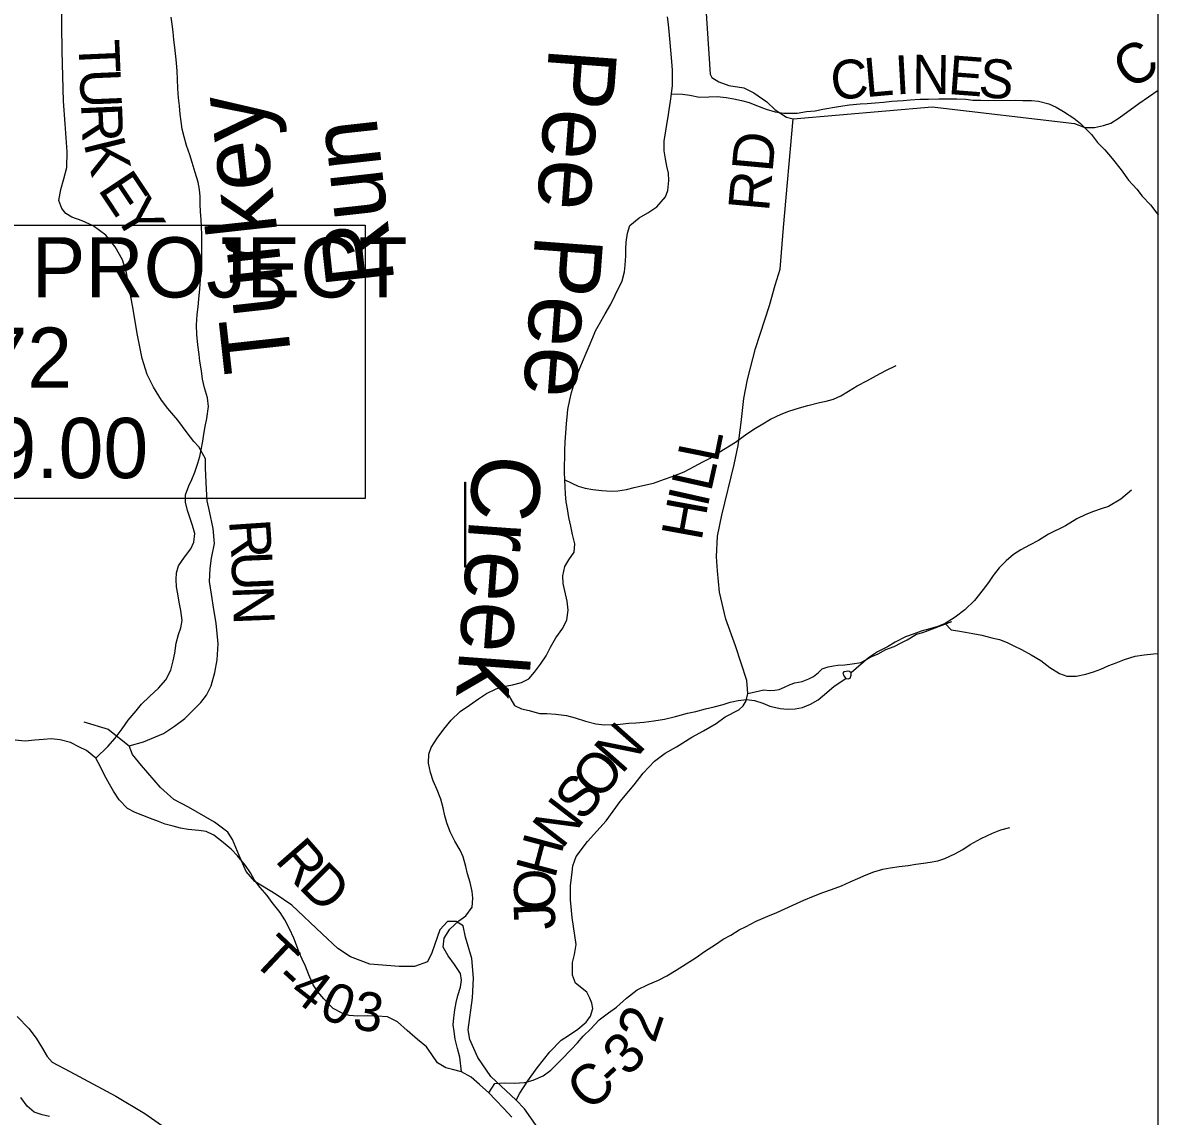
# Model space of a CAD drawing. Extents: x -139 to 835, y 0 to 440.
# Drawn here: x 242.7 to 295.5, y 238 to 288.9 of the extents above; entities that cross this region are included whole.
import ezdxf

# ---------------------------------------------------------------- set-up
doc = ezdxf.new("R2010")
doc.units = 0
for name, color, linetype in [('GM_X_County_Road', 7, 'Continuous'), ('GM_X_County_Road_Text', 7, 'Continuous'), ('GM_X_County_Text', 7, 'Continuous'), ('GM_X_Major_River', 7, 'Continuous'), ('GM_X_Minor_Lake', 7, 'Continuous'), ('GM_X_Minor_River', 7, 'Continuous'), ('GM_X_Minor_River_Text', 7, 'Continuous'), ('GM_X_Township_Road', 7, 'Continuous'), ('GM_X_Township_Road_Text', 7, 'Continuous'), ('SH_Cut_Line', 7, 'Continuous'), ('SH_Text', 7, 'Continuous')]:
    doc.layers.add(name, color=color, linetype=linetype)

msp = doc.modelspace()

# ---------------------------------------------------------------- linework, layer by layer
at = {"layer": 'GM_X_County_Road'}
for points in [[(274.092, 294.765), (274.624, 286.489), (274.713, 286.332), (275.03, 286.138), (275.5, 285.968), (276.199, 285.857), (276.656, 285.627), (277.265, 285.203), (277.658, 284.828), (278.178, 284.489), (278.496, 284.408), (284.945, 284.976), (291.568, 284.197), (292.051, 284.015), (292.496, 284.002), (292.916, 284.097), (293.247, 284.205), (293.642, 284.457), (294.56, 285.118), (295.458, 285.75)], [(265.617, 238.775), (265.793, 239.107), (266.164, 239.673), (266.586, 240.287), (267.186, 241.033), (267.709, 241.563), (268.04, 241.791), (268.486, 242.079), (268.869, 242.404), (269.073, 242.681), (269.177, 243.042), (269.139, 243.284), (269.038, 243.525), (268.899, 243.803), (268.379, 244.215), (268.241, 244.589), (268.23, 245.18), (268.333, 245.554), (268.398, 246.024), (268.211, 247.267), (268.138, 248.088), (268.14, 248.739), (268.218, 249.378), (268.245, 249.667), (268.399, 250.113), (268.935, 250.8), (269.791, 251.774), (270.455, 252.665), (270.854, 253.154), (271.093, 253.447), (271.515, 253.977), (272.051, 254.542), (272.535, 254.915), (273.07, 255.215), (273.784, 255.659), (274.319, 255.947), (274.918, 256.295), (275.326, 256.596), (275.963, 256.931), (276.167, 257.112), (276.307, 257.341), (276.385, 257.69), (276.336, 258.294), (275.807, 259.9), (275.366, 261.143), (275.065, 262.399), (274.967, 263.4), (274.931, 264.04), (274.972, 265.005), (275.166, 265.981), (275.746, 268.332), (275.927, 269.224), (276.071, 270.297), (276.202, 271.406), (276.37, 272.286), (276.744, 273.733), (277.386, 275.734), (277.656, 276.674), (277.888, 277.421), (278.047, 279.362), (278.496, 284.408)], [(242.419, 242.661), (242.964, 242.104), (243.306, 241.657), (243.559, 241.258), (243.812, 240.811), (244.053, 240.545), (244.865, 240.108), (247.01, 238.968), (248.356, 238.156), (249.13, 237.623)], [(264.633, 229.287), (265.055, 229.63), (265.697, 230.03), (266.36, 230.621), (266.883, 231.135), (267.285, 231.345), (267.666, 231.402), (268.289, 231.497), (269.012, 232.259), (269.314, 232.964), (269.314, 233.498), (269.173, 234.146), (268.912, 234.831), (268.671, 235.193), (268.309, 235.536), (267.727, 236.108), (267.285, 236.546), (266.622, 237.499), (265.999, 238.375), (265.617, 238.775)]]:
    msp.add_lwpolyline(points, dxfattribs=at)
at = {"layer": 'GM_X_County_Text'}
msp.add_lwpolyline([(138.399, 185.387), (295.458, 185.387), (295.458, 319.381), (267.909, 321.538), (228.151, 324.569)], dxfattribs=at)
at = {"layer": 'GM_X_Major_River'}
msp.add_lwpolyline([(243.924, 238.019), (243.581, 238.094), (243.213, 238.217), (242.885, 238.497), (242.595, 238.909)], dxfattribs=at)
at = {"layer": 'GM_X_Minor_Lake'}
for points in [[(281.111, 258.716), (281.035, 258.728), (280.946, 258.715), (280.844, 258.69), (280.794, 258.641), (280.846, 258.509), (280.936, 258.389), (281.051, 258.366), (281.14, 258.403), (281.189, 258.548), (281.191, 258.644)], [(281.191, 258.644), (281.111, 258.716)]]:
    msp.add_lwpolyline(points, dxfattribs=at)
at = {"layer": 'GM_X_Minor_River'}
for points in [[(246.074, 254.681), (246.642, 255.217), (246.982, 255.606), (247.309, 256.043), (247.585, 256.444), (247.95, 256.881), (248.202, 257.185), (248.568, 257.551), (248.997, 257.941), (249.337, 258.318), (249.562, 258.766), (249.672, 259.201), (249.758, 259.564), (249.818, 260.035), (249.916, 260.434), (250.027, 260.749), (250.088, 261.087), (250.033, 261.545), (249.953, 261.93), (249.886, 262.316), (249.832, 262.641), (249.816, 262.991), (249.826, 263.293), (249.924, 263.631), (250.201, 264.032), (250.49, 264.421), (250.64, 264.724), (250.674, 265.134), (250.569, 265.507), (250.464, 265.832), (250.346, 266.205), (250.241, 266.59), (250.25, 266.928), (250.399, 267.339), (250.537, 267.642), (250.686, 267.981), (250.822, 268.405), (250.908, 268.707), (250.969, 269.021), (251.055, 269.42), (251.103, 269.747), (251.163, 270.097), (251.236, 270.472), (251.32, 271.027), (251.265, 271.437), (251.134, 271.906), (251.041, 272.304), (250.986, 272.689), (250.919, 273.135), (250.878, 273.448), (250.822, 273.906), (250.767, 274.376), (250.763, 274.81), (250.784, 275.305), (250.832, 275.668), (250.867, 276.018), (250.913, 276.513), (250.947, 276.935), (250.982, 277.322), (251.004, 277.732), (251, 278.082), (251.008, 278.613), (251.005, 279.011), (250.988, 279.385), (250.973, 279.71), (250.944, 280.096), (250.928, 280.422), (250.925, 280.796), (250.896, 281.121), (250.842, 281.47), (250.698, 281.916), (250.554, 282.373), (250.448, 282.734), (250.292, 283.166), (250.186, 283.576), (250.094, 283.937), (250.04, 284.286), (249.998, 284.624), (249.969, 285.009), (249.928, 285.395), (249.898, 285.817), (249.869, 286.251), (249.853, 286.625), (249.824, 287.011), (249.795, 287.312), (249.753, 287.722), (249.712, 288.083), (249.67, 288.457), (249.629, 288.806), (249.588, 289.132)], [(270.68, 277.61), (270.714, 278.033), (270.711, 278.346), (270.721, 278.672), (270.794, 279.095), (270.905, 279.446), (271.334, 279.812), (271.739, 280.045), (272.157, 280.326), (272.56, 280.776), (272.671, 281.079), (272.705, 281.55), (272.69, 281.887), (272.623, 282.212), (272.556, 282.549), (272.489, 282.923), (272.498, 283.369), (272.57, 283.852), (272.618, 284.154), (272.678, 284.505), (272.726, 284.831), (272.786, 285.23), (272.834, 285.58), (272.881, 285.966), (272.874, 286.678), (272.845, 287.076), (272.817, 287.438), (272.759, 288.137), (272.731, 288.474), (272.689, 288.8), (272.648, 289.149)], [(272.834, 285.58), (273.343, 285.56), (273.687, 285.515), (274.133, 285.423), (274.566, 285.439), (274.96, 285.455), (275.381, 285.41), (275.725, 285.341), (276.082, 285.26), (276.439, 285.167), (276.784, 285.037), (277.231, 284.86), (277.652, 284.743), (278.06, 284.675), (278.671, 284.68), (279.116, 284.745), (279.51, 284.785), (279.865, 284.86), (280.602, 284.988), (281.111, 285.065), (281.607, 285.105), (281.925, 285.12), (282.306, 285.148), (282.688, 285.188), (283.082, 285.227), (283.603, 285.268), (283.934, 285.296), (284.379, 285.324), (284.786, 285.327), (285.257, 285.344), (285.69, 285.348), (286.097, 285.339), (286.517, 285.319), (286.836, 285.286), (287.205, 285.277), (287.587, 285.269), (288.821, 285.28), (289.165, 285.271), (289.559, 285.263), (289.891, 285.229), (290.375, 285.101), (290.708, 284.947), (291.053, 284.758), (291.527, 284.448), (291.847, 284.198), (292.361, 283.684), (292.632, 283.312), (292.979, 282.966), (293.313, 282.559), (293.725, 282.032), (294.073, 281.552), (294.459, 281.146), (294.716, 280.822), (295.102, 280.416), (295.398, 280.02), (295.458, 279.952)], [(263.071, 240.093), (263.001, 240.78), (262.896, 241.177), (262.777, 241.622), (262.736, 241.972), (262.695, 242.285), (262.717, 242.611), (262.765, 242.986), (262.825, 243.312), (262.911, 243.638), (263.022, 244.025), (263.07, 244.364), (263.029, 244.665), (262.745, 245.085), (262.449, 245.492), (262.216, 245.9), (262.276, 246.311), (262.526, 246.735), (262.943, 247.113), (263.272, 247.345), (263.573, 247.758), (263.608, 248.169), (263.567, 248.482), (263.474, 248.904), (263.355, 249.301), (263.276, 249.638), (263.157, 250.095), (263.014, 250.408), (262.769, 250.828), (262.548, 251.248), (262.392, 251.669), (262.3, 251.994), (262.22, 252.367), (262.114, 252.776), (261.945, 253.209), (261.763, 253.629), (261.632, 254.014), (261.539, 254.448), (261.561, 254.87), (261.66, 255.173), (261.948, 255.61), (262.25, 256.023), (262.602, 256.448), (263.019, 256.85), (263.449, 257.143), (263.866, 257.437), (264.233, 257.681), (264.689, 257.903), (265.019, 258.014), (265.451, 258.091), (265.87, 258.203), (266.199, 258.363), (266.463, 258.679), (266.74, 259.056), (267.004, 259.444), (267.204, 259.844), (267.454, 260.281), (267.781, 260.73), (267.968, 261.118), (268.028, 261.565), (267.986, 261.987), (267.8, 262.805), (267.784, 263.155), (267.882, 263.59), (268.057, 263.905), (268.308, 264.258), (268.343, 264.644), (268.237, 265.077), (268.157, 265.463), (268.064, 265.872), (267.997, 266.269), (267.943, 266.595), (267.902, 266.956), (267.886, 267.294), (267.87, 267.62), (267.854, 267.981), (267.864, 268.307), (267.873, 268.645), (267.883, 268.995), (267.892, 269.393), (267.927, 269.792), (267.961, 270.238), (267.983, 270.54), (268.018, 270.89), (268.103, 271.35), (268.189, 271.688), (268.275, 271.991), (268.424, 272.438), (268.548, 272.741), (268.698, 273.116), (268.872, 273.516), (269.009, 273.843), (269.171, 274.243), (269.308, 274.545), (269.483, 274.873), (269.746, 275.346), (270.009, 275.794), (270.209, 276.206), (270.534, 276.885), (270.645, 277.296), (270.68, 277.61)], [(267.87, 267.62), (268.497, 267.324), (268.816, 267.23), (269.185, 267.173), (269.593, 267.129), (270.026, 267.096), (270.344, 267.111), (270.738, 267.175), (271.106, 267.275), (271.5, 267.363), (271.995, 267.476), (272.515, 267.65), (272.858, 267.774), (273.416, 267.996), (273.884, 268.242), (274.289, 268.462), (274.631, 268.634), (275.049, 268.904), (275.808, 269.369), (276.339, 269.76), (276.744, 270.029), (277.086, 270.225), (277.44, 270.446), (277.934, 270.679), (278.289, 270.815), (278.784, 270.977), (279.178, 271.077), (279.711, 271.214), (280.029, 271.278), (280.359, 271.377), (280.701, 271.525), (281.055, 271.746), (281.46, 271.99), (281.941, 272.236), (282.359, 272.469), (282.803, 272.702), (283.271, 272.948)], [(294.206, 267.137), (293.714, 266.722), (293.144, 266.379), (292.801, 266.268), (292.446, 266.144), (292.091, 266.008), (291.673, 265.811), (291.141, 265.48), (290.356, 265.099), (289.888, 264.805), (289.47, 264.584), (289.077, 264.363), (288.736, 264.155), (288.382, 263.862), (288.067, 263.534), (287.79, 263.169), (287.564, 262.853), (287.312, 262.525), (286.923, 262.015), (286.468, 261.577), (286.013, 261.235), (285.558, 260.941), (285.216, 260.805), (284.848, 260.693), (284.441, 260.581), (284.112, 260.469), (283.706, 260.321), (283.224, 260.075), (282.87, 259.855), (282.414, 259.633), (281.984, 259.34), (281.191, 258.644)], [(285.558, 260.941), (285.828, 260.642), (286.147, 260.596), (286.504, 260.539), (286.835, 260.482), (287.256, 260.402), (287.728, 260.273), (288.072, 260.204), (288.442, 260.063), (288.775, 259.897), (289.094, 259.731), (289.555, 259.494), (290.003, 259.22), (290.413, 258.898), (290.874, 258.625), (291.206, 258.495), (291.638, 258.487), (292.083, 258.588), (292.451, 258.7), (292.781, 258.824), (293.161, 258.984), (293.504, 259.12), (293.884, 259.268), (294.379, 259.417), (294.798, 259.482), (295.231, 259.534), (295.458, 259.545)], [(265.019, 258.014), (265.536, 257.126), (265.868, 256.973), (266.225, 256.891), (266.698, 256.763), (267.041, 256.754), (267.461, 256.722), (267.958, 256.666), (268.354, 256.561), (268.839, 256.409), (269.311, 256.28), (269.719, 256.236), (270.062, 256.251), (270.444, 256.266), (270.85, 256.306), (271.181, 256.321), (271.55, 256.349), (272.008, 256.413), (272.503, 256.502), (273.024, 256.616), (273.582, 256.778), (273.963, 256.854), (274.421, 256.978), (274.814, 257.066), (275.233, 257.179), (275.563, 257.29), (275.931, 257.366), (276.326, 257.406), (276.695, 257.361), (277.078, 257.244), (277.397, 257.102), (277.882, 256.986), (278.226, 256.965), (278.582, 256.968), (278.925, 257.032), (279.293, 257.192), (279.647, 257.4), (280.051, 257.742), (280.392, 258.022), (280.936, 258.389)], [(245.319, 255.192), (244.897, 255.406), (244.425, 255.534), (244.004, 255.579), (243.648, 255.551), (243.241, 255.511), (242.796, 255.471), (242.325, 255.515)], [(265.407, 237.991), (265.047, 238.386), (264.661, 238.792), (264.34, 239.115), (263.916, 239.509), (263.519, 239.844), (263.071, 240.093), (262.663, 240.198), (262.344, 240.279), (261.96, 240.517), (261.689, 240.901), (261.444, 241.26), (261.034, 241.606), (260.546, 242.012), (260.097, 242.418), (259.637, 242.655), (259.153, 242.687), (258.695, 242.695), (258.249, 242.679), (257.855, 242.712), (257.523, 242.829), (257.113, 243.043), (256.677, 243.497), (256.394, 243.82), (256.187, 244.144), (255.979, 244.601), (255.823, 245.009), (255.667, 245.334), (255.537, 245.646), (255.406, 245.983), (255.289, 246.307), (255.081, 246.74), (254.861, 247.16), (254.642, 247.508), (254.268, 247.975), (254.036, 248.299), (253.715, 248.67), (253.457, 249.005), (253.263, 249.353), (253.031, 249.689), (252.67, 250.144), (252.375, 250.455), (252.003, 250.753), (251.567, 251.099), (251.209, 251.265), (250.865, 251.31), (250.368, 251.366), (250.011, 251.423), (249.667, 251.516), (249.31, 251.61), (248.99, 251.739), (248.62, 251.869), (247.905, 252.152), (247.559, 252.342), (247.161, 252.736), (246.903, 253.144), (246.709, 253.468), (246.489, 253.888), (246.294, 254.272), (246.074, 254.681), (245.651, 255.039), (245.319, 255.192)], [(264.34, 239.115), (264.629, 239.552), (265.061, 239.58), (265.519, 239.572), (266.015, 239.601), (266.409, 239.701), (266.865, 239.91), (267.219, 240.179), (267.711, 240.654), (268.178, 241.129), (268.467, 241.445), (268.732, 241.749), (269.085, 242.102), (269.476, 242.516), (269.905, 242.834), (270.272, 243.102), (270.739, 243.517), (271.245, 243.908), (271.751, 244.154), (272.233, 244.363), (272.613, 244.559), (273.056, 244.817), (273.511, 245.123), (273.98, 245.416), (274.372, 245.685), (274.878, 246.016), (275.232, 246.26), (275.586, 246.457), (275.979, 246.702), (276.308, 246.861), (276.764, 247.095), (277.309, 247.329), (277.728, 247.502), (278.108, 247.674), (278.475, 247.846), (278.982, 248.08), (279.439, 248.265), (279.87, 248.438), (280.276, 248.575), (280.732, 248.748), (281.138, 248.932), (281.493, 249.093), (281.886, 249.253), (282.241, 249.389), (282.66, 249.513), (283.003, 249.577), (283.409, 249.641), (283.829, 249.693), (284.197, 249.745), (284.541, 249.796), (284.858, 249.847), (285.214, 249.911), (285.544, 250.01), (286, 250.232), (286.367, 250.44), (286.722, 250.661), (287.228, 250.943), (287.76, 251.201), (288.141, 251.349), (288.56, 251.462)]]:
    msp.add_lwpolyline(points, dxfattribs=at)
at = {"layer": 'GM_X_Township_Road'}
for points in [[(265.617, 238.775), (264.432, 239.88), (263.829, 240.756), (263.467, 241.595), (263.387, 242.052), (263.588, 243.538), (263.628, 244.452), (263.548, 245.367), (263.266, 246.358), (263.146, 246.891), (262.825, 247.082), (262.423, 247.082), (262.061, 246.701), (261.7, 245.634), (261.499, 245.215), (260.896, 244.986), (260.173, 244.986), (258.807, 245.1), (257.923, 245.443), (257.32, 245.824), (256.597, 246.51), (255.19, 247.844), (254.467, 248.339), (253.463, 248.949), (253.061, 249.406), (252.739, 250.149), (252.438, 250.892), (252.217, 251.235), (251.594, 251.711), (250.389, 252.397), (249.706, 252.759), (249.083, 253.312), (248.199, 254.34), (247.777, 254.855), (247.636, 255.255), (248.299, 255.445), (249.229, 255.826), (249.738, 256.162), (250.21, 256.523), (250.58, 256.884), (250.963, 257.268), (251.231, 257.618), (251.436, 258.051), (251.616, 258.666), (251.72, 259.257), (251.76, 259.992), (251.675, 260.958), (251.562, 261.597), (251.45, 262.309), (251.363, 262.901), (251.391, 263.504), (251.456, 263.986), (251.598, 264.661), (251.537, 265.361), (251.361, 266.17), (251.261, 266.652), (251.225, 267.195), (251.177, 268.161), (251.179, 268.607), (250.863, 269.151), (250.635, 269.405), (250.318, 269.816), (249.888, 270.396), (249.432, 270.94), (249.128, 271.327), (248.761, 271.931), (248.47, 272.523), (248.231, 273.26), (248.019, 274.358), (247.782, 275.734), (247.632, 276.554), (247.507, 277.254), (247.318, 277.858), (246.977, 278.462), (246.547, 278.994), (245.95, 279.442), (245.442, 279.673), (244.96, 279.831), (244.681, 280.013), (244.503, 280.242), (244.365, 280.617), (244.455, 281.123), (244.597, 281.617), (244.726, 282.148), (244.741, 282.871), (244.656, 284.186), (244.584, 285.236), (244.515, 287.564), (244.485, 289.977)], [(279.592, 258.604), (279.644, 258.646), (279.835, 258.839), (280.115, 258.934), (280.357, 258.982), (280.56, 259.006), (280.891, 259.029), (281.234, 259.064), (281.642, 259.135), (282.075, 259.375), (282.432, 259.531), (282.801, 259.735), (283.183, 259.879), (283.501, 260.047), (283.782, 260.191), (284.215, 260.443), (284.52, 260.526), (285.857, 261.029)], [(276.385, 257.69), (277.123, 257.857), (277.39, 257.82), (277.632, 257.844), (277.835, 257.879), (278.09, 257.975), (278.357, 258.107), (278.574, 258.191), (278.904, 258.25), (279.223, 258.37), (279.439, 258.478), (279.592, 258.604)], [(245.517, 256.371), (246.652, 256.028), (247.636, 255.255)]]:
    msp.add_lwpolyline(points, dxfattribs=at)
at = {"layer": 'SH_Cut_Line'}
msp.add_lwpolyline([(67.578, 336.518), (67.578, 185.387), (295.458, 185.387), (295.458, 319.381), (267.909, 321.538), (228.151, 324.569), (207.436, 326.102), (194.287, 327.176), (177.155, 328.576), (171.559, 329.033), (160.688, 329.921), (158.444, 330.1), (105.67, 333.828), (92.493, 334.759)], close=True, dxfattribs=at)
at = {"layer": 'SH_Text'}
for points in [[(230.034, 279.464), (258.605, 279.464), (258.605, 266.754), (230.034, 266.754)], [(263.267, 263.558), (263.228, 263.558), (263.228, 267.519), (263.267, 267.519)]]:
    msp.add_lwpolyline(points, close=True, dxfattribs=at)

# ---------------------------------------------------------------- texts
at = {"layer": 'GM_X_County_Road_Text'}
for s, height, rotation, p in [('C', 1.855, 34.0298, (294.165, 285.714)), ('C', 1.807, 5.1, (280.308, 285.278)), ('L', 1.807, 5.1, (281.865, 285.417)), ('I', 1.806, 3.206, (283.266, 285.542)), ('N', 1.806, 359.4199, (284.011, 285.585)), ('E', 1.807, 355.6333, (285.652, 285.57)), ('S', 1.808, 353.7386, (287.054, 285.463)), ('RD', 1.9039, 84.8066, (277.361, 280.061)), ('L', 1.903, 78.5992, (274.972, 268.377)), ('L', 1.903, 77.3918, (274.668, 267.018)), ('I', 1.903, 77.3676, (274.505, 266.292)), ('H', 1.903, 79.6662, (274.224, 264.744)), ('N', 1.881, 48.5442, (270.516, 253.895)), ('O', 1.884, 50.9708, (269.508, 252.65)), ('S', 1.884, 51.0391, (268.726, 251.684)), ('N', 1.886, 52.3606, (267.744, 250.41)), ('H', 1.902, 75.0175, (267.413, 249.034)), ('O', 1.904, 89.3201, (267.41, 247.558)), ('J', 1.904, 92.3773, (267.445, 246.735)), ('2', 1.901, 71.2844, (272.057, 241.377)), ('3', 1.876, 45.5144, (270.8, 239.822)), ('C', 1.871, 42.3761, (269.033, 238.199)), ('-', 1.872, 42.8144, (270.172, 239.237))]:
    msp.add_text(s, height=height, rotation=rotation, dxfattribs=at).set_placement(p)
at = {"layer": 'GM_X_Minor_River_Text'}
for s, height, rotation, p in [('Pee Pee', 3.1734, 265.762, (267.147, 287.784)), ('Turkey', 3.1732, 96.3237, (255.226, 272.79)), ('Run', 3.1732, 96.3238, (259.968, 276.817)), ('Creek', 3.1736, 265.7617, (263.66, 268.87))]:
    msp.add_text(s, height=height, rotation=rotation, dxfattribs=at).set_placement(p)
at = {"layer": 'GM_X_Township_Road_Text'}
for s, height, rotation, p in [('T', 1.904, 272.4771, (245.261, 288.053)), ('U', 1.904, 272.4767, (245.319, 286.704)), ('R', 1.904, 272.4576, (245.388, 285.116)), ('K', 1.903, 283.8538, (245.503, 283.272)), ('E', 1.891, 303.5713, (246.145, 281.134)), ('Y', 1.893, 301.2081, (246.894, 280.007)), ('R', 1.904, 273.8008, (252.268, 265.736)), ('U', 1.904, 272.3552, (252.366, 264.267)), ('N', 1.904, 272.19, (252.431, 262.681)), ('R', 1.881, 311.1641, (254.365, 249.914)), ('D', 1.875, 315.127, (255.456, 248.672)), ('T', 1.872, 316.6863, (253.263, 245.262)), ('-', 1.871, 317.4198, (254.292, 244.292)), ('4', 1.862, 322.2108, (254.984, 243.666)), ('0', 1.831, 337.5695, (256.378, 242.681)), ('3', 1.809, 351.7426, (257.968, 242.096))]:
    msp.add_text(s, height=height, rotation=rotation, dxfattribs=at).set_placement(p)
at = {"layer": 'SH_Text'}
for s, p in [('BEGIN PROJECT', (230.407, 276.104)), ('S.R. 772             ', (230.407, 271.904)), ('SLM 19.00         ', (230.407, 267.704))]:
    msp.add_text(s, height=2.79999, dxfattribs=at).set_placement(p)

doc.saveas('drawing.dxf')
